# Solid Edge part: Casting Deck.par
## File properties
Username: m_hel
Author: m_hel
Template: Iso Metric Part.par
Last saved by: m_hel
Revision: 4
Application: Solid Edge
Accuracy: 0,990
Material: Textured White
Face Style: White painted
Fill Style: ANSI36(Marble)
Virtual Style: ANSI36(Marble)
Grouping: Uncategorized
LibraryName: Custom Materials
Coef. of Thermal Exp: 0.0
Thermal Conductivity: 0.0
Specific Heat: 0.0
Modulus of Elasticity: 0.0
Poisson's Ratio: 0.0
Yield Stress: 0.0
Ultimate Stress: 0.0
Elongation: 0.0
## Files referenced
..\Redfisher18.asm
G:\OneDriveTemp\OneDrive\Dokumendid\TLÜ tööd\3D Modelleerimine\3d modelling\veesõiduk\Back Rails.par
iduk\Back Rails.par
iduk\Redfisher18.asm
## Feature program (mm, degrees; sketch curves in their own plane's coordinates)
sketch for "unnamed Protrusion 1" plane through (0, 0, 0) normal (0, 0, 1) x-axis (1, 0, 0)
  line (-418.0761, -301.4762) -> (-418.0761, -134.676)
  arc centre (-283.4001, -134.676) radius 134.676 from (-418.0761, -134.676) to (-401.782, -70.4626) cw
  arc centre (-283.4001, -134.676) radius 134.676 from (-401.782, -70.4626) to (-331.782, -8.9906) cw
  arc centre (-283.4001, -134.676) radius 134.676 from (-331.782, -8.9906) to (-283.4001, 0) cw
  line (-283.4001, 0) -> (-35, 0)
  line (-35, 0) -> (35, 0)
  line (35, 0) -> (283.4001, 0)
  arc centre (283.4001, -128.5238) radius 128.5238 from (283.4001, 0) to (331.782, -9.4542) cw
  arc centre (283.4001, -128.5238) radius 128.5238 from (331.782, -9.4542) to (401.782, -78.4829) cw
  arc centre (283.4001, -128.5238) radius 128.5238 from (401.782, -78.4829) to (411.9239, -128.5238) cw
  line (411.9239, -128.5238) -> (411.9239, -295.324)
  arc centre (277.2479, -295.324) radius 134.676 from (411.9239, -295.324) to (401.782, -346.5966) cw
  arc centre (277.2479, -295.324) radius 134.676 from (401.782, -346.5966) to (331.782, -418.4648) cw
  arc centre (277.2479, -295.324) radius 134.676 from (331.782, -418.4648) to (277.2479, -430) cw
  line (277.2479, -430) -> (35, -430)
  line (35, -430) -> (-35, -430)
  line (-35, -430) -> (-289.5524, -430)
  arc centre (-289.5524, -301.4762) radius 128.5238 from (-289.5524, -430) to (-331.782, -422.8641) cw
  arc centre (-289.5524, -301.4762) radius 128.5238 from (-331.782, -422.8641) to (-401.782, -364.109) cw
  arc centre (-289.5524, -301.4762) radius 128.5238 from (-401.782, -364.109) to (-418.0761, -301.4762) cw
extrude "unnamed Protrusion 1" add finite 30 along +normal
fillet "Round_3" radius 20
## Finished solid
Body 1: solid body, 18 faces, 40 edges, 24 vertices.
  Faces by surface: cylinder 8, plane 6, torus 4
  Edges by curve: circle 20, line 20
Bounding box of the edges (mm; curved faces can reach further): 830.000 x 430.000 x 30.000, from (-418.0761, -430, 0) to (411.9239, 0, 30).
Cylindrical faces by radius (mm): R20 x4, R128.5238 x2, R134.676 x2
Toroidal faces (ring radius, tube radius in mm): R108.5238 r20 x2, R114.676 r20 x2
Planar faces by outward normal: +x 1, +y 1, +z 1, -x 1, -y 1, -z 1
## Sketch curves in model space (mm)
arc centre (-289.5524, -301.4762, 0) radius 128.5238 from (-289.5524, -430, 0) through (-310.9665, -428.2035, 0) to (-331.782, -422.8641, 0)
arc centre (-289.5524, -301.4762, 0) radius 128.5238 from (-331.782, -422.8641, 0) through (-372.1808, -399.9186, 0) to (-401.782, -364.109, 0)
arc centre (-289.5524, -301.4762, 0) radius 128.5238 from (-401.782, -364.109, 0) through (-413.9359, -333.835, 0) to (-418.0761, -301.4762, 0)
line (-418.0761, -301.4762, 0) -> (-418.0761, -134.676, 0)
arc centre (-283.4001, -134.676, 0) radius 134.676 from (-418.0761, -134.676, 0) through (-413.939, -101.5518, 0) to (-401.782, -70.4626, 0)
arc centre (-283.4001, -134.676, 0) radius 134.676 from (-401.782, -70.4626, 0) through (-372.2665, -33.4812, 0) to (-331.782, -8.9906, 0)
arc centre (-283.4001, -134.676, 0) radius 134.676 from (-331.782, -8.9906, 0) through (-308.0052, -2.2667, 0) to (-283.4001, 0, 0)
line (-283.4001, 0, 0) -> (-35, 0, 0)
line (-35, 0, 0) -> (35, 0, 0)
line (35, 0, 0) -> (283.4001, 0, 0)
arc centre (283.4001, -128.5238, 0) radius 128.5238 from (283.4001, 0, 0) through (308.0486, -2.3857, 0) to (331.782, -9.4542, 0)
arc centre (283.4001, -128.5238, 0) radius 128.5238 from (331.782, -9.4542, 0) through (373.643, -37.011, 0) to (401.782, -78.4829, 0)
arc centre (283.4001, -128.5238, 0) radius 128.5238 from (401.782, -78.4829, 0) through (409.3629, -102.9946, 0) to (411.9239, -128.5238, 0)
line (411.9239, -128.5238, 0) -> (411.9239, -295.324, 0)
arc centre (277.2479, -295.324, 0) radius 134.676 from (411.9239, -295.324, 0) through (409.3641, -321.457, 0) to (401.782, -346.5966, 0)
arc centre (277.2479, -295.324, 0) radius 134.676 from (401.782, -346.5966, 0) through (373.7239, -389.2921, 0) to (331.782, -418.4648, 0)
arc centre (277.2479, -295.324, 0) radius 134.676 from (331.782, -418.4648, 0) through (305.1183, -427.0846, 0) to (277.2479, -430, 0)
line (277.2479, -430, 0) -> (35, -430, 0)
line (35, -430, 0) -> (-35, -430, 0)
line (-35, -430, 0) -> (-289.5524, -430, 0)
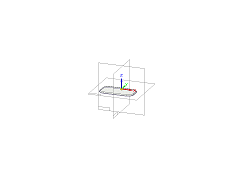
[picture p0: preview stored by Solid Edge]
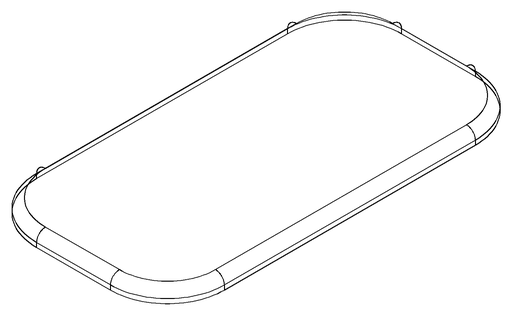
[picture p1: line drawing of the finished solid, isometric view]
